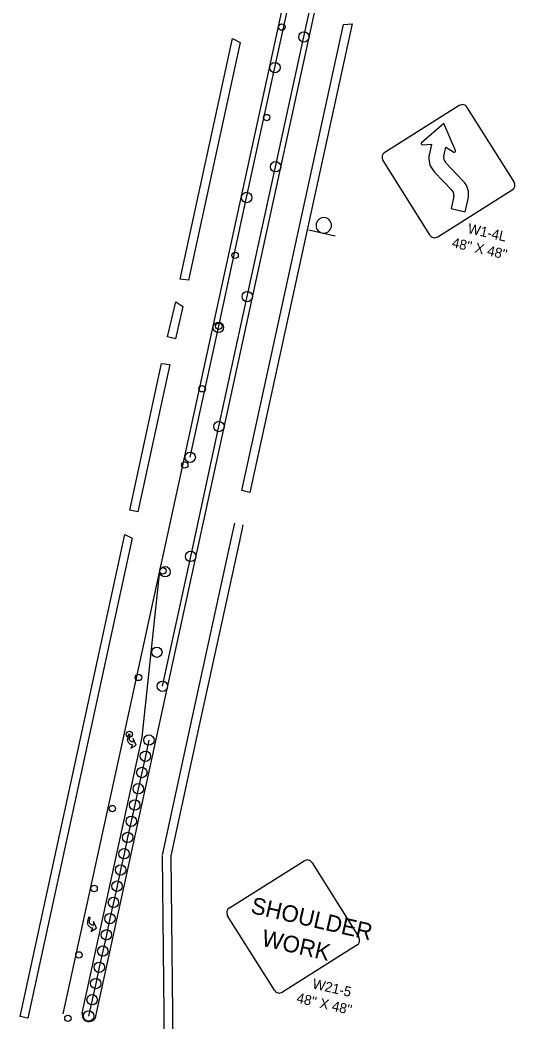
# Model space of a CAD drawing. Extents: x 1615924 to 1617091, y 899733 to 904714.
# Drawn here: x 1616397 to 1616695, y 900741 to 901344 of the extents above; entities that cross this region are included whole.
import ezdxf

# ---------------------------------------------------------------- set-up
doc = ezdxf.new("R2010")
doc.units = 0
for name, color, linetype in [('DEV PSS CELL', 7, 'Continuous'), ('MARK LEFT TURN ARROW CELL', 7, 'Continuous'), ('Prop Conc 4in Sidewalk', 7, 'Continuous'), ('Prop Mkg 3ft Min Skp 9ft White', 7, 'Continuous'), ('Prop Mkg Solid Yellow Diagonals', 7, 'Continuous'), ('Prop Mkg Solid Yellow Edge Line', 7, 'Continuous'), ('Scratch_Level_7', 7, 'Continuous'), ('Scratch_Level_8', 7, 'Continuous'), ('Stage 2 Barrells', 7, 'Continuous'), ('WS W1-4L CELL', 7, 'Continuous'), ('WS W21-5 CELL', 7, 'Continuous')]:
    doc.layers.add(name, color=color, linetype=linetype)

msp = doc.modelspace()

# ---------------------------------------------------------------- linework, layer by layer
at = {"layer": 'DEV PSS CELL'}
msp.add_line((1616571.38, 901218.03), (1616587.17, 901214.41), dxfattribs=at)
msp.add_arc((1616580.32, 901220.77), 4.67, 260.05107, 256.88427, dxfattribs=at)
at = {"layer": 'MARK LEFT TURN ARROW CELL'}
for p, q in [((1616568.33, 901334.21), (1616585.33, 901412.39)), ((1616550.89, 901315.71), (1616567.9, 901393.88)), ((1616551.29, 901256.05), (1616568.33, 901334.21)), ((1616533.89, 901237.53), (1616550.89, 901315.71)), ((1616534.26, 901177.88), (1616551.29, 901256.05)), ((1616516.89, 901159.36), (1616533.89, 901237.53)), ((1616517.22, 901099.72), (1616534.26, 901177.88)), ((1616499.89, 901081.19), (1616516.89, 901159.36)), ((1616500.18, 901021.55), (1616517.22, 901099.72)), ((1616483.15, 900943.39), (1616500.18, 901021.55)), ((1616475.07, 900910.99), (1616472.93, 900901.22)), ((1616472.93, 900901.22), (1616470.8, 900891.45)), ((1616470.8, 900891.45), (1616468.66, 900881.68)), ((1616468.66, 900881.68), (1616466.52, 900871.91)), ((1616466.52, 900871.91), (1616464.39, 900862.14)), ((1616464.39, 900862.14), (1616462.25, 900852.37)), ((1616462.25, 900852.37), (1616460.11, 900842.6)), ((1616460.11, 900842.6), (1616457.98, 900832.83)), ((1616457.98, 900832.83), (1616455.84, 900823.06)), ((1616455.84, 900823.06), (1616453.7, 900813.3)), ((1616453.7, 900813.3), (1616451.57, 900803.53)), ((1616451.57, 900803.53), (1616449.43, 900793.76)), ((1616449.43, 900793.76), (1616447.29, 900783.99)), ((1616447.29, 900783.99), (1616445.16, 900774.22)), ((1616445.16, 900774.22), (1616443.02, 900764.45)), ((1616443.02, 900764.45), (1616440.88, 900754.68)), ((1616440.88, 900754.68), (1616438.75, 900744.91))]:
    msp.add_line(p, q, dxfattribs=at)
at = {"layer": 'Prop Conc 4in Sidewalk'}
for p, q in [((1616531.01, 901061.12), (1616592.14, 901341.73)), ((1616597.32, 901342.02), (1616535.89, 901060.06)), ((1616592.14, 901341.73), (1616597.32, 901342.02)), ((1616493.89, 901188.45), (1616525.28, 901333.16)), ((1616525.28, 901333.16), (1616529.91, 901330.9)), ((1616529.91, 901330.9), (1616498.84, 901187.8)), ((1616498.84, 901187.8), (1616493.89, 901188.45)), ((1616486.17, 901153.64), (1616491.15, 901174.68)), ((1616495.37, 901171.95), (1616491.06, 901152.57)), ((1616491.15, 901174.68), (1616495.37, 901171.95)), ((1616491.06, 901152.57), (1616486.17, 901153.64)), ((1616463.47, 901049.43), (1616482.69, 901137.66)), ((1616487.66, 901136.98), (1616468.35, 901048.36)), ((1616482.83, 901137.58), (1616487.66, 901136.98)), ((1616535.89, 901060.06), (1616531.01, 901061.12)), ((1616468.35, 901048.36), (1616463.47, 901049.43)), ((1616463.47, 901049.43), (1616463.47, 901049.43)), ((1616524.59, 901031.69), (1616526.75, 901041.58)), ((1616531.63, 901040.52), (1616529.48, 901030.63)), ((1616397.45, 900744.69), (1616460.51, 901034.67)), ((1616465.02, 901032.56), (1616402.19, 900743.66)), ((1616460.51, 901034.67), (1616465.02, 901032.56)), ((1616500.17, 900919.59), (1616524.59, 901031.69)), ((1616529.48, 901030.63), (1616505.15, 900918.94)), ((1616483.22, 900841.77), (1616500.17, 900919.59)), ((1616505.15, 900918.94), (1616488.22, 900841.26)), ((1616484.52, 900726.82), (1616483.17, 900841.32)), ((1616488.22, 900841.26), (1616488.18, 900840.81)), ((1616488.18, 900840.81), (1616489.51, 900727.87)), ((1616402.19, 900743.66), (1616397.45, 900744.69))]:
    msp.add_line(p, q, dxfattribs=at)
at = {"layer": 'Prop Mkg 3ft Min Skp 9ft White'}
for centre in [(1616568.33, 901334.21), (1616568.33, 901334.21), (1616550.89, 901315.71), (1616550.89, 901315.71), (1616551.29, 901256.05), (1616551.29, 901256.05), (1616533.89, 901237.53), (1616533.89, 901237.53), (1616534.26, 901177.88), (1616534.26, 901177.88), (1616516.89, 901159.36), (1616516.89, 901159.36), (1616517.22, 901099.72), (1616517.22, 901099.72), (1616499.89, 901081.19), (1616499.89, 901081.19), (1616500.18, 901021.55), (1616500.18, 901021.55), (1616484.8, 901012.3), (1616484.8, 901012.3), (1616479.83, 900963.87), (1616479.83, 900963.87), (1616483.15, 900943.39), (1616483.15, 900943.39), (1616475.07, 900910.99), (1616475.07, 900910.99), (1616472.93, 900901.22), (1616472.93, 900901.22), (1616470.8, 900891.45), (1616470.8, 900891.45), (1616468.66, 900881.68), (1616468.66, 900881.68), (1616466.52, 900871.91), (1616466.52, 900871.91), (1616464.39, 900862.14), (1616464.39, 900862.14), (1616462.25, 900852.37), (1616462.25, 900852.37), (1616460.11, 900842.6), (1616460.11, 900842.6), (1616457.98, 900832.83), (1616457.98, 900832.83), (1616455.84, 900823.06), (1616455.84, 900823.06), (1616453.7, 900813.3), (1616453.7, 900813.3), (1616451.57, 900803.53), (1616451.57, 900803.53), (1616449.43, 900793.76), (1616449.43, 900793.76), (1616447.29, 900783.99), (1616447.29, 900783.99), (1616445.16, 900774.22), (1616445.16, 900774.22), (1616443.02, 900764.45), (1616443.02, 900764.45), (1616440.88, 900754.68), (1616440.88, 900754.68), (1616438.75, 900744.91), (1616438.75, 900744.91)]:
    msp.add_circle(centre, 3.13, dxfattribs=at)
at = {"layer": 'Prop Mkg Solid Yellow Diagonals'}
for points in [[(1616463.69, 900914.39), (1616462.71, 900914.62), (1616462.14, 900912.1), (1616462.06, 900911.63), (1616462.04, 900911.26), (1616462.07, 900910.85), (1616462.17, 900910.49), (1616462.28, 900910.2), (1616462.48, 900909.82), (1616462.68, 900909.55), (1616462.92, 900909.25), (1616463.25, 900908.93), (1616463.53, 900908.74), (1616463.91, 900908.52), (1616464.46, 900908.32), (1616465.25, 900908.14), (1616464.1, 900906.09), (1616467.43, 900907.98), (1616465.62, 900911.99), (1616465.6, 900909.68), (1616464.95, 900909.83), (1616464.59, 900909.93), (1616464.28, 900910.1), (1616464.04, 900910.29), (1616463.75, 900910.56), (1616463.56, 900910.8), (1616463.38, 900911.18), (1616463.28, 900911.59), (1616463.22, 900911.99), (1616463.26, 900912.53)], [(1616463.69, 900914.4), (1616462.71, 900914.62), (1616462.14, 900912.1), (1616462.06, 900911.63), (1616462.04, 900911.26), (1616462.07, 900910.85), (1616462.17, 900910.49), (1616462.28, 900910.21), (1616462.48, 900909.82), (1616462.68, 900909.55), (1616462.92, 900909.25), (1616463.25, 900908.93), (1616463.53, 900908.74), (1616463.91, 900908.52), (1616464.46, 900908.32), (1616465.25, 900908.14), (1616464.1, 900906.1), (1616467.44, 900907.98), (1616465.62, 900911.99), (1616465.6, 900909.68), (1616464.95, 900909.83), (1616464.59, 900909.93), (1616464.28, 900910.1), (1616464.04, 900910.29), (1616463.75, 900910.56), (1616463.56, 900910.8), (1616463.38, 900911.18), (1616463.28, 900911.59), (1616463.22, 900911.99), (1616463.26, 900912.53)], [(1616439.67, 900804.15), (1616438.7, 900804.37), (1616438.12, 900801.85), (1616438.04, 900801.38), (1616438.02, 900801.01), (1616438.05, 900800.6), (1616438.15, 900800.24), (1616438.26, 900799.96), (1616438.46, 900799.57), (1616438.66, 900799.3), (1616438.9, 900799), (1616439.23, 900798.68), (1616439.51, 900798.49), (1616439.9, 900798.27), (1616440.45, 900798.07), (1616441.23, 900797.89), (1616440.08, 900795.85), (1616443.42, 900797.73), (1616441.6, 900801.74), (1616441.58, 900799.43), (1616440.93, 900799.58), (1616440.57, 900799.69), (1616440.26, 900799.85), (1616440.02, 900800.04), (1616439.73, 900800.31), (1616439.54, 900800.55), (1616439.36, 900800.93), (1616439.26, 900801.34), (1616439.2, 900801.74), (1616439.24, 900802.28)], [(1616439.67, 900804.15), (1616438.7, 900804.37), (1616438.12, 900801.85), (1616438.04, 900801.38), (1616438.02, 900801.01), (1616438.05, 900800.6), (1616438.15, 900800.24), (1616438.26, 900799.96), (1616438.46, 900799.57), (1616438.66, 900799.3), (1616438.9, 900799), (1616439.23, 900798.69), (1616439.51, 900798.49), (1616439.9, 900798.27), (1616440.45, 900798.07), (1616441.23, 900797.89), (1616440.08, 900795.85), (1616443.42, 900797.73), (1616441.6, 900801.74), (1616441.58, 900799.43), (1616440.93, 900799.58), (1616440.57, 900799.69), (1616440.26, 900799.86), (1616440.03, 900800.04), (1616439.73, 900800.31), (1616439.54, 900800.55), (1616439.36, 900800.93), (1616439.26, 900801.34), (1616439.2, 900801.74), (1616439.24, 900802.28)]]:
    msp.add_lwpolyline(points, close=True, dxfattribs=at)
at = {"layer": 'Prop Mkg Solid Yellow Edge Line'}
for p, q in [((1616443.17, 900744.86), (1616587.62, 901407.9)), ((1616471.05, 900912.77), (1616481.59, 901012.82)), ((1616434.87, 900746.66), (1616471.05, 900912.77))]:
    msp.add_line(p, q, dxfattribs=at)
msp.add_lwpolyline([(1616481.59, 901012.82), (1616585.09, 901487.91)], dxfattribs=at)
msp.add_arc((1616439.02, 900745.76), 4.25, 167.70978, 347.70978, dxfattribs=at)
at = {"layer": 'Scratch_Level_7'}
msp.add_line((1616423.51, 900746.24), (1616460.3, 900915.11), dxfattribs=at)
at = {"layer": 'Scratch_Level_8'}
msp.add_line((1616460.3, 900915.11), (1616481.59, 901012.82), dxfattribs=at)
at = {"layer": 'Stage 2 Barrells'}
for centre in [(1616555.07, 901340.13), (1616545.91, 901285.65), (1616526.93, 901202.72), (1616517.16, 901160.04), (1616507.12, 901122.43), (1616496.61, 901076.52), (1616483.47, 901012.84), (1616468.78, 900948.67), (1616463.27, 900914.43), (1616453.04, 900869.75), (1616442.03, 900821.65), (1616432.88, 900781.66), (1616426.28, 900743.53)]:
    msp.add_circle(centre, 1.93, dxfattribs=at)
at = {"layer": 'WS W1-4L CELL'}
for p, q in [((1616652.6, 901282.01), (1616639.2, 901270.43)), ((1616659.56, 901265.77), (1616652.6, 901282.01)), ((1616639.67, 901269.25), (1616645.24, 901269.7)), ((1616645.24, 901269.7), (1616643.89, 901263.81)), ((1616652.58, 901262.39), (1616653.81, 901267.74)), ((1616653.81, 901267.74), (1616658.64, 901264.91)), ((1616664.31, 901247.45), (1616653.61, 901258.69)), ((1616646.83, 901253.03), (1616657.6, 901241.77)), ((1616648.88, 901213.9), (1616693.78, 901242.07)), ((1616658.56, 901238.09), (1616656.91, 901230.89)), ((1616665.41, 901228.95), (1616667.2, 901236.76)), ((1616656.91, 901230.89), (1616665.41, 901228.95))]:
    msp.add_line(p, q, dxfattribs=at)
for points in [[(1616661.88, 901292.89), (1616616.99, 901264.72)], [(1616694.88, 901246.89), (1616666.71, 901291.79)], [(1616615.89, 901259.9), (1616644.06, 901215)]]:
    msp.add_lwpolyline(points, dxfattribs=at)
for centre, radius, start, end in [((1616663.75, 901289.93), 3.5, 77.10192, 122.10843), ((1616663.75, 901289.93), 3.5, 32.0954, 77.10192), ((1616639.67, 901269.92), 0.665, 131.01622, 269.67811), ((1616618.85, 901261.76), 3.5, 122.10843, 212.10843), ((1616655.34, 901261.15), 11.76, 167.10843, 223.53106), ((1616656.51, 901261.49), 4.02, 167.10843, 223.53095), ((1616658.93, 901265.51), 0.665, 244.53875, 23.20064), ((1616655.77, 901239.36), 11.76, 347.10843, 43.53106), ((1616691.92, 901245.03), 3.5, 302.10843, 32.10843), ((1616654.64, 901238.98), 4.02, 347.10843, 43.53123), ((1616647.02, 901216.86), 3.5, 212.10843, 257.10843), ((1616647.02, 901216.86), 3.5, 257.10843, 302.10843)]:
    msp.add_arc(centre, radius, start, end, dxfattribs=at)
at = {"layer": 'WS W21-5 CELL'}
msp.add_line((1616600.31, 900787.46), (1616555.41, 900759.29), dxfattribs=at)
for points in [[(1616523.52, 900810.11), (1616568.41, 900838.28)], [(1616573.24, 900837.18), (1616601.41, 900792.28)], [(1616550.59, 900760.39), (1616522.42, 900805.29)]]:
    msp.add_lwpolyline(points, dxfattribs=at)
for centre, start, end in [((1616570.27, 900835.32), 77.10192, 122.10843), ((1616570.27, 900835.32), 32.0954, 77.10192), ((1616525.38, 900807.15), 122.10843, 212.10843), ((1616598.45, 900790.42), 302.10843, 32.10843), ((1616553.55, 900762.25), 212.10843, 257.10843), ((1616553.55, 900762.25), 257.10843, 302.10843)]:
    msp.add_arc(centre, 3.5, start, end, dxfattribs=at)

# ---------------------------------------------------------------- texts
at = {"layer": 'WS W1-4L CELL'}
for s, p in [('W1-4L', (1616666.58, 901216.22)), ("48'' X 48''", (1616657.03, 901207.71))]:
    msp.add_text(s, height=6, rotation=347.10843, dxfattribs=at).set_placement(p)
at = {"layer": 'WS W21-5 CELL'}
for s, height, p in [('SHOULDER', 10, (1616535.82, 900806.97)), ('WORK', 10, (1616542.31, 900787.32)), ('W21-5', 6, (1616573.11, 900761.61)), ("48'' X 48''", 6, (1616563.55, 900753.1))]:
    msp.add_text(s, height=height, rotation=347.10843, dxfattribs=at).set_placement(p)

doc.saveas('drawing.dxf')
